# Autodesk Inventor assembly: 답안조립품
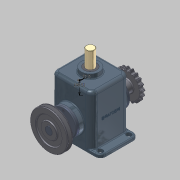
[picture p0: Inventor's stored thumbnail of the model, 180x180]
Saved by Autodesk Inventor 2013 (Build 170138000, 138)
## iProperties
Created: 2015-01
Part Number: 답안조립품
Document SubType Name: Assembly
Designer: Administrator
Author: Administrator
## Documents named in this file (15)
- C:\Users\Administrator\Desktop\350106V1031\답안조립품.iam
- C:\Users\Administrator\Desktop\350106V1031\본체.ipt
- C:\Users\Administrator\Desktop\350106V1031\커버.ipt
- C:\Users\Administrator\Desktop\350106V1031\오일실.ipt
- C:\Users\Administrator\Desktop\350106V1031\M4x0.5.ipt
- C:\Users\Administrator\Desktop\350106V1031\베어링 6205.ipt
- C:\Users\Administrator\Desktop\350106V1031\편심축.ipt
- C:\Users\Administrator\Desktop\350106V1031\멈춤링.ipt
- C:\Users\Administrator\Desktop\350106V1031\키 8x8.ipt
- C:\Users\Administrator\Desktop\350106V1031\V-벨트풀리.ipt
- C:\Users\Administrator\Desktop\350106V1031\체인 스프로킷.ipt
- C:\Users\Administrator\Desktop\350106V1031\멈춤나사 M5x0.5.ipt
- C:\Users\Administrator\Desktop\350106V1031\부시.ipt
- C:\Users\Administrator\Desktop\350106V1031\슬라이드.ipt
- C:\Users\Administrator\Desktop\350106V1031\7-가변스프링.ipt
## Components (9 placed, 4 different names)
1. V-벨트풀리:1 — 플러쉬:2
2. 5-체인 스프로킷:1 — 플러쉬:1
3. 7-가변스프링:1
4. M4x0.5:2
5. M4x0.5:3
6. M4x0.5:4
7. M4x0.5:1
8. M4x0.5:5
9. M4x0.5:6
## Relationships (2: Flush 2)
- 플러쉬:1 [Flush]: 5-체인 스프로킷:1
- 플러쉬:2 [Flush]: V-벨트풀리:1
